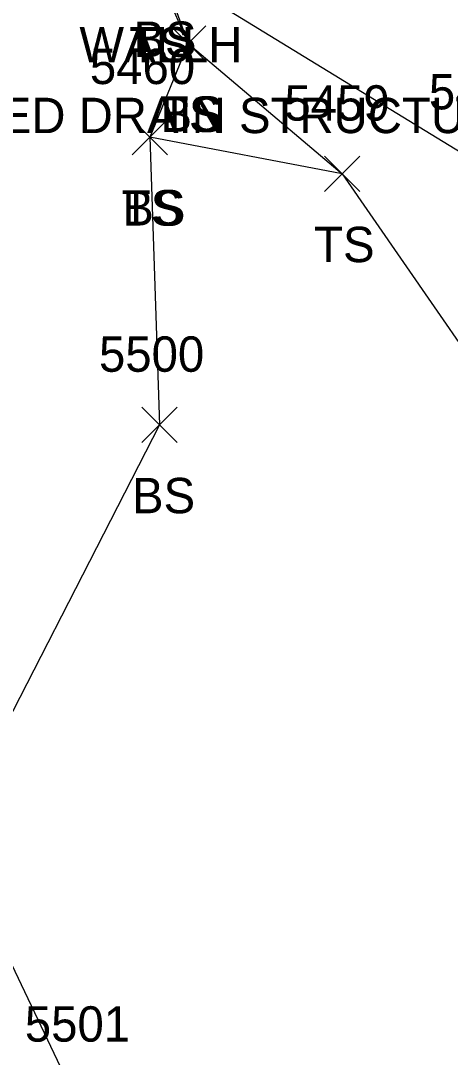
# Model space of a CAD drawing. Extents: x 1601151 to 1602912, y 499508 to 501770.
# Drawn here: x 1601575.6 to 1601599.8, y 500825.3 to 500883.9 of the extents above; entities that cross this region are included whole.
import ezdxf

# ---------------------------------------------------------------- set-up
doc = ezdxf.new("R2010")
doc.units = 0
for name, color, linetype in [('D_A', 7, 'Continuous'), ('D_C', 7, 'Continuous'), ('L_A', 7, 'Continuous'), ('L_I', 7, 'Continuous'), ('L_TIC', 7, 'Continuous'), ('LAWA', 7, 'Continuous'), ('LELB', 7, 'Continuous')]:
    doc.layers.add(name, color=color, linetype=linetype)

msp = doc.modelspace()

# ---------------------------------------------------------------- linework, layer by layer
at = {"layer": 'L_TIC'}
for points in [[(1601584.018, 500881.655), (1601586.018, 500883.655)], [(1601586.018, 500881.655), (1601584.018, 500883.655)], [(1601584.018, 500881.655), (1601586.018, 500883.655)], [(1601586.018, 500881.655), (1601584.018, 500883.655)], [(1601581.86, 500876.357), (1601583.86, 500878.357)], [(1601583.86, 500876.357), (1601581.86, 500878.357)], [(1601581.86, 500876.357), (1601583.86, 500878.357)], [(1601583.86, 500876.357), (1601581.86, 500878.357)], [(1601592.731, 500874.289), (1601594.731, 500876.289)], [(1601594.731, 500874.289), (1601592.731, 500876.289)], [(1601582.407, 500860.091), (1601584.407, 500862.091)], [(1601584.407, 500860.091), (1601582.407, 500862.091)]]:
    msp.add_lwpolyline(points, dxfattribs=at)
at = {"layer": 'LAWA'}
msp.add_lwpolyline([(1601593.118, 500801.876), (1601578.563, 500823.216), (1601571.541, 500837.943), (1601571.618, 500859.309), (1601565.589, 500876.721), (1601544.544, 500946.966)], dxfattribs=at)
at = {"layer": 'LELB'}
for points in [[(1601502.321, 501150.223), (1601505.899, 501145.217), (1601526.181, 501094.759), (1601535.634, 501063.325), (1601547.72, 501037.545), (1601557.168, 500997.586), (1601569.357, 500953.231), (1601577.101, 500908.294), (1601582.384, 500892.077), (1601583.485, 500886.894), (1601585.018, 500882.655), (1601582.86, 500877.357), (1601583.407, 500861.091), (1601571.541, 500837.943)], [(1601569.357, 500953.231), (1601593.676, 500909.128), (1601604.076, 500885.582), (1601583.485, 500886.894), (1601601.367, 500875.926), (1601606.028, 500857.494), (1601615.046, 500803.704)], [(1601604.076, 500885.582), (1601589.354, 500894.773), (1601582.384, 500892.077), (1601583.284, 500886.583), (1601585.018, 500882.655), (1601593.731, 500875.289), (1601582.86, 500877.357)], [(1601593.731, 500875.289), (1601606.028, 500857.494)]]:
    msp.add_lwpolyline(points, dxfattribs=at)

# ---------------------------------------------------------------- texts
at = {"layer": 'D_A'}
msp.add_text('WALLH', height=2, dxfattribs=at).set_placement((1601578.875, 500881.583))
at = {"layer": 'D_C'}
msp.add_text('CENTER UNUSED DRAIN STRUCTURE-N', height=2, dxfattribs=at).set_placement((1601555.056, 500877.583))
at = {"layer": 'L_A'}
for s, p in [('TS', (1601581.694, 500881.583)), ('BS', (1601581.926, 500881.894)), ('BS', (1601581.926, 500881.894)), ('TS', (1601583.427, 500877.655)), ('BS', (1601583.459, 500877.655)), ('TS', (1601581.269, 500872.357)), ('BS', (1601581.301, 500872.357)), ('TS', (1601592.14, 500870.289)), ('BS', (1601581.848, 500856.091))]:
    msp.add_text(s, height=2, dxfattribs=at).set_placement(p)
at = {"layer": 'L_I'}
for s, p in [('5460', (1601579.466, 500880.357)), ('5460', (1601579.466, 500880.357)), ('5461', (1601598.627, 500878.926)), ('5459', (1601590.463, 500878.289)), ('5500', (1601579.982, 500864.091)), ('5501', (1601575.791, 500826.216))]:
    msp.add_text(s, height=2, dxfattribs=at).set_placement(p)

doc.saveas('drawing.dxf')
